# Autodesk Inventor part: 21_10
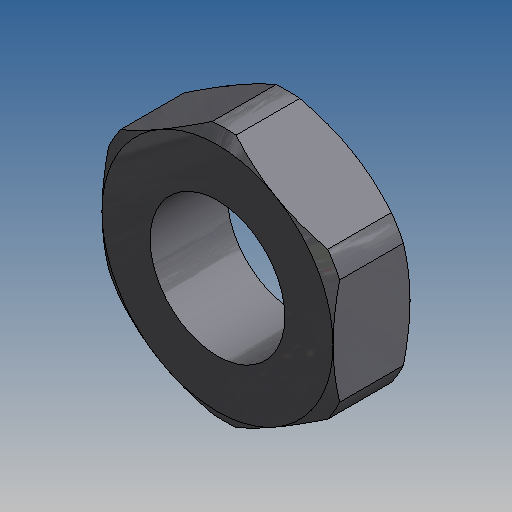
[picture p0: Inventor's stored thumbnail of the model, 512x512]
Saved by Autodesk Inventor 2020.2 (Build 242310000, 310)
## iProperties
Part Number: 21_10
Material: Generic
Document SubType Name: Modeling
Designer: amoles
Appearance: Default
Author: amoles
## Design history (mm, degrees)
feature "Base1"
body "Solid1"
